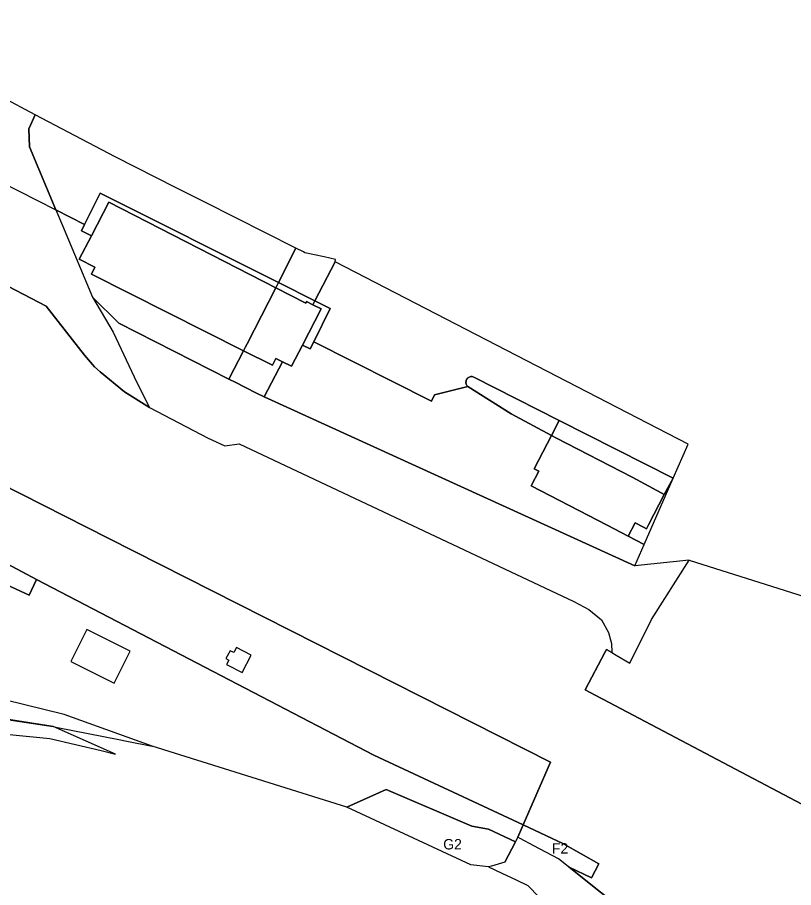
# Model space of a CAD drawing. Extents: x -749314 to -746497, y -1026537 to -1024935.
# Drawn here: x -748054 to -747867.9, y -1025476.4 to -1025267.7 of the extents above; entities that cross this region are included whole.
import ezdxf

# ---------------------------------------------------------------- set-up
doc = ezdxf.new("R2010")
doc.units = 0
for name, color, linetype in [('Default', 7, 'Continuous'), ('K_CD1', 7, 'Continuous'), ('K_DOSZDC1', 7, 'Continuous'), ('K_JVL', 7, 'Continuous'), ('K_NH_SZDC', 7, 'Continuous'), ('K_SZDC1', 7, 'Continuous')]:
    doc.layers.add(name, color=color, linetype=linetype)

msp = doc.modelspace()

# ---------------------------------------------------------------- linework, layer by layer
at = {"layer": 'Default'}
for points in [[(-748259.36, -1025267.68), (-748156.97, -1025329.23), (-748032.2, -1025392.56), (-747926.21, -1025446.35), (-747932.75, -1025461.36), (-747968.57, -1025444.62), (-748049.38, -1025402.52), (-748073.99, -1025389.35), (-748082.88, -1025385.8), (-748108.65, -1025372.85), (-748143.78, -1025358.9), (-748153.5, -1025355.12), (-748164.65, -1025351.55), (-748174.46, -1025348.85), (-748184.1, -1025347.37), (-748182.63, -1025341.82), (-748186.39, -1025340.76), (-748185.38, -1025333.16), (-748213.73, -1025328.27), (-748213.86, -1025329.03), (-748217.05, -1025328.49), (-748217.16, -1025329.19), (-748227.91, -1025325.68), (-748255.65, -1025319)], [(-748057.97, -1025307.14), (-748044.75, -1025313.87), (-748043.19, -1025317.58), (-748035.96, -1025334.78), (-748030.99, -1025343.14), (-748025.38, -1025355.27), (-748022.3, -1025361.24), (-748028.3, -1025357.47), (-748034.14, -1025352.71), (-748035.54, -1025351.47), (-748037.89, -1025348.71), (-748047.05, -1025336.96), (-748057.96, -1025331.28)]]:
    msp.add_lwpolyline(points, dxfattribs=at)
for points in [[(-748035.41, -1025327.58), (-748039.16, -1025325.69), (-748036.26, -1025320.08), (-748038.64, -1025318.9), (-748037.89, -1025317.39), (-748044.75, -1025313.87), (-748043.19, -1025317.58), (-748035.96, -1025334.78), (-748029.7, -1025341.02), (-748003.33, -1025354.49), (-747999.79, -1025347.62), (-748036.24, -1025329.23)], [(-748035.96, -1025334.78), (-748030.99, -1025343.14), (-748025.38, -1025355.27), (-748022.3, -1025361.24), (-748008.28, -1025368.63), (-748004.23, -1025370.41), (-748000.86, -1025369.98), (-747920.59, -1025407.75), (-747917, -1025409.72), (-747913.96, -1025412.2), (-747912.26, -1025415.21), (-747911.57, -1025417.86), (-747911.52, -1025420.04), (-747910.44, -1025420.66), (-747907.16, -1025422.53), (-747901.99, -1025412.07), (-747892.92, -1025397.87), (-747905.98, -1025399.2), (-747994.84, -1025358.7), (-747996.8, -1025357.7), (-748001.6, -1025355.25), (-748003.33, -1025354.49), (-748029.7, -1025341.02)], [(-747945.99, -1025356.21), (-747954.01, -1025358.24), (-747954.73, -1025359.75), (-747982.95, -1025345.52), (-747983.79, -1025347.2), (-747985.65, -1025346.26), (-747988.28, -1025351.35), (-747990.41, -1025350.28), (-747994.84, -1025358.7), (-747905.98, -1025399.2), (-747903.74, -1025394.11), (-747907.58, -1025392.1), (-747912.58, -1025389.5), (-747930.82, -1025380), (-747929.02, -1025376.53), (-747930.09, -1025375.97), (-747925.95, -1025367.99), (-747935.59, -1025362.74)], [(-747994.84, -1025358.7), (-747990.41, -1025350.28), (-747992.03, -1025349.46), (-747992.86, -1025351.11), (-747999.79, -1025347.62), (-748003.33, -1025354.49), (-748001.6, -1025355.25), (-747996.8, -1025357.7)], [(-747924.14, -1025364.33), (-747944.59, -1025353.94), (-747944.94, -1025353.84), (-747945.31, -1025353.84), (-747945.66, -1025353.94), (-747945.98, -1025354.14), (-747946.09, -1025354.24), (-747946.31, -1025354.54), (-747946.44, -1025354.88), (-747946.47, -1025355.25), (-747946.4, -1025355.61), (-747946.24, -1025355.94), (-747945.99, -1025356.21), (-747935.59, -1025362.74), (-747925.95, -1025367.99)], [(-747898.92, -1025382.15), (-747896.76, -1025378.2), (-747924.14, -1025364.33), (-747925.95, -1025367.99), (-747924.88, -1025368.55), (-747906.59, -1025377.99), (-747899.69, -1025381.75)], [(-747898.92, -1025382.15), (-747902.66, -1025389.38), (-747903.15, -1025390.32), (-747903.92, -1025389.92), (-747905.9, -1025388.91), (-747907.58, -1025392.1), (-747903.74, -1025394.11), (-747896.76, -1025378.2)], [(-747997.91, -1025420.63), (-748001.49, -1025418.81), (-748002.12, -1025420.05), (-748003, -1025419.61), (-748003.98, -1025421.48), (-748003.29, -1025421.83), (-748003.83, -1025422.9), (-748000.07, -1025424.84)], [(-748003.98, -1025421.48), (-748003.29, -1025421.83), (-748003.83, -1025422.9), (-748000.07, -1025424.84), (-747997.91, -1025420.63), (-748001.49, -1025418.81), (-748002.12, -1025420.05), (-748003, -1025419.61)], [(-747974.99, -1025457.07), (-747965.57, -1025452.88), (-747945.01, -1025461.7), (-747941.02, -1025462.36), (-747934.61, -1025465.41), (-747937.12, -1025470.28), (-747940.3, -1025471.24), (-747941.01, -1025471.45), (-747945.26, -1025470.98)], [(-747930.17, -1025466.36), (-747933.49, -1025464.6), (-747934.04, -1025464.31), (-747937.12, -1025470.28), (-747940.3, -1025471.24), (-747941.01, -1025471.45), (-747937.86, -1025472.92), (-747934.45, -1025474.52), (-747931.59, -1025475.86), (-747928.91, -1025478.73), (-747876.17, -1025514.34), (-747839.67, -1025538.87), (-747860, -1025524.32), (-747873.67, -1025507.89), (-747876.37, -1025512.29), (-747887.27, -1025505.61), (-747884.53, -1025501.19), (-747924.24, -1025469.51)]]:
    msp.add_lwpolyline(points, close=True, dxfattribs=at)
at = {"layer": 'K_CD1'}
for points in [[(-747992.07, -1025332.51), (-747991.43, -1025331.25), (-748034.12, -1025309.81), (-748037.89, -1025317.39), (-748038.64, -1025318.9), (-748036.26, -1025320.08), (-748032.06, -1025311.97)], [(-747999.41, -1025346.89), (-747998.94, -1025345.97), (-747992.07, -1025332.51), (-748032.06, -1025311.97), (-748036.26, -1025320.08), (-748039.16, -1025325.69), (-748035.41, -1025327.58), (-748036.24, -1025329.23), (-747999.79, -1025347.62)], [(-747988.28, -1025351.35), (-747985.65, -1025346.26), (-747981.19, -1025337.62), (-747983.2, -1025336.59), (-747984.66, -1025335.84), (-747984.85, -1025336.21), (-747992.07, -1025332.51), (-747998.94, -1025345.97), (-747999.41, -1025346.89), (-747999.79, -1025347.62), (-747992.86, -1025351.11), (-747992.03, -1025349.46), (-747990.41, -1025350.28)], [(-747983.2, -1025336.59), (-747982.7, -1025335.64), (-747991.43, -1025331.25), (-747992.07, -1025332.51), (-747984.85, -1025336.21), (-747984.66, -1025335.84)], [(-747982.7, -1025335.64), (-747983.2, -1025336.59), (-747981.19, -1025337.62), (-747985.65, -1025346.26), (-747983.79, -1025347.2), (-747982.95, -1025345.52), (-747978.97, -1025337.51)], [(-748115.84, -1025423.38), (-748116.01, -1025426.66), (-748045.39, -1025437.77), (-748044.41, -1025437.98), (-748029.7, -1025440.89), (-748027.77, -1025441.28), (-748021.66, -1025442.5), (-748042.77, -1025434.89), (-748061.7, -1025430.24), (-748111.52, -1025421.94), (-748150.48, -1025415.41), (-748150.78, -1025415.18), (-748163.17, -1025405.57), (-748151.61, -1025420.44), (-748137.8, -1025422.95), (-748137.76, -1025422.13)], [(-748149.03, -1025434.28), (-748138.93, -1025443.46), (-748137.83, -1025443.74), (-748131.63, -1025445.33), (-748123.33, -1025444.53), (-748094.04, -1025441.72), (-748063.99, -1025438.84), (-748046.18, -1025440.63), (-748033.92, -1025443.55), (-748030.5, -1025444.36), (-748045.39, -1025437.77), (-748064.07, -1025434.97), (-748084.21, -1025436.6), (-748123.99, -1025441.67), (-748131.48, -1025440.38), (-748138.81, -1025436.89), (-748151.61, -1025420.44), (-748166.47, -1025409.42)], [(-748026.92, -1025419.73), (-748037.3, -1025414.46), (-748041.17, -1025422.13), (-748030.77, -1025427.38)], [(-748026.92, -1025419.73), (-748037.3, -1025414.46), (-748041.17, -1025422.13), (-748030.77, -1025427.38)], [(-748151.61, -1025420.44), (-748138.81, -1025436.89), (-748131.48, -1025440.38), (-748123.99, -1025441.67), (-748084.21, -1025436.6), (-748064.07, -1025434.97), (-748045.39, -1025437.77), (-748116.01, -1025426.66), (-748116.07, -1025427.79), (-748115.16, -1025427.84), (-748115.25, -1025429.55), (-748116.16, -1025429.5), (-748116.6, -1025437.71), (-748138.47, -1025436.54), (-748138.19, -1025430.94), (-748139.96, -1025430.85), (-748139.84, -1025427.7), (-748138.04, -1025427.78), (-748137.8, -1025422.95)], [(-747884.53, -1025501.19), (-747924.24, -1025469.51), (-747930.17, -1025466.36), (-747933.49, -1025464.6), (-747934.04, -1025464.31), (-747926.21, -1025446.35), (-747932.75, -1025461.36), (-747923.1, -1025465.87), (-747914.56, -1025470.67), (-747916.35, -1025474.07), (-747921.73, -1025471.52)]]:
    msp.add_lwpolyline(points, close=True, dxfattribs=at)
for points in [[(-748073.99, -1025389.35), (-748049.38, -1025402.52), (-748051.19, -1025406.25), (-748070.97, -1025397.13)], [(-748070.97, -1025397.13), (-748051.19, -1025406.25), (-748049.38, -1025402.52), (-747968.57, -1025444.62), (-747932.75, -1025461.36), (-747934.04, -1025464.31), (-747937.12, -1025470.28), (-747934.61, -1025465.41), (-747941.02, -1025462.36), (-747945.01, -1025461.7), (-747965.57, -1025452.88), (-747974.99, -1025457.07), (-748021.66, -1025442.5), (-748042.77, -1025434.89), (-748061.7, -1025430.24)]]:
    msp.add_lwpolyline(points, dxfattribs=at)
at = {"layer": 'K_DOSZDC1'}
for points in [[(-747860, -1025524.32), (-747873.67, -1025507.89), (-747884.53, -1025501.19), (-747921.73, -1025471.52), (-747916.35, -1025474.07), (-747914.56, -1025470.67), (-747923.1, -1025465.87), (-747932.75, -1025461.36), (-747926.21, -1025446.35), (-748032.2, -1025392.56), (-748156.97, -1025329.23), (-748259.36, -1025267.68)], [(-748057.96, -1025331.28), (-748047.05, -1025336.96), (-748037.89, -1025348.71), (-748035.54, -1025351.47), (-748034.14, -1025352.71), (-748028.3, -1025357.47), (-748022.3, -1025361.24), (-748008.28, -1025368.63), (-748004.23, -1025370.41), (-748000.86, -1025369.98), (-747920.59, -1025407.75), (-747917, -1025409.72), (-747913.96, -1025412.2), (-747912.26, -1025415.21), (-747911.57, -1025417.86), (-747911.52, -1025420.04), (-747912.78, -1025419.32), (-747913.16, -1025420.04), (-747917.87, -1025428.97), (-747915.46, -1025430.24), (-747912.12, -1025432), (-747865.91, -1025456.37)], [(-747645.99, -1025568.28), (-747732.3, -1025526.84), (-747772.49, -1025505.64), (-747865.91, -1025456.37), (-747912.12, -1025432), (-747915.46, -1025430.24), (-747917.87, -1025428.97), (-747913.16, -1025420.04), (-747912.78, -1025419.32), (-747911.52, -1025420.04), (-747910.44, -1025420.66), (-747907.16, -1025422.53), (-747901.99, -1025412.07), (-747892.92, -1025397.87), (-747869.93, -1025405.14), (-747846.49, -1025412.54), (-747841.03, -1025414.26), (-747808.54, -1025424.53), (-747801.54, -1025426.74), (-747806.89, -1025440.81), (-747803.65, -1025456.55), (-747724.81, -1025501.31), (-747681.55, -1025522.63), (-747651.76, -1025538.04)]]:
    msp.add_lwpolyline(points, dxfattribs=at)
at = {"layer": 'K_JVL'}
msp.add_lwpolyline([(-748057.97, -1025307.14), (-748044.75, -1025313.87), (-748051.12, -1025298.75), (-748051.28, -1025294.41), (-748049.7, -1025291.02), (-748065.92, -1025282.45)], dxfattribs=at)
for points in [[(-748037.89, -1025317.39), (-748034.12, -1025309.81), (-747991.43, -1025331.25), (-747987.22, -1025323.01), (-748009.05, -1025311.99), (-748015.9, -1025308.53), (-748030.54, -1025301.15), (-748049.7, -1025291.02), (-748051.28, -1025294.41), (-748051.12, -1025298.75), (-748044.75, -1025313.87)], [(-747982.7, -1025335.64), (-747977.81, -1025326.34), (-747977.7, -1025325.73), (-747980.41, -1025325.13), (-747985.06, -1025324.11), (-747985.41, -1025323.93), (-747987.22, -1025323.01), (-747991.43, -1025331.25)], [(-747978.97, -1025337.51), (-747982.95, -1025345.52), (-747954.73, -1025359.75), (-747954.01, -1025358.24), (-747945.99, -1025356.21), (-747946.24, -1025355.94), (-747946.4, -1025355.61), (-747946.47, -1025355.25), (-747946.44, -1025354.88), (-747946.39, -1025354.73), (-747946.23, -1025354.41), (-747945.98, -1025354.14), (-747945.66, -1025353.94), (-747945.31, -1025353.84), (-747944.94, -1025353.84), (-747944.59, -1025353.94), (-747924.14, -1025364.33), (-747896.76, -1025378.2), (-747893.2, -1025370.08), (-747977.81, -1025326.34), (-747982.7, -1025335.64)]]:
    msp.add_lwpolyline(points, close=True, dxfattribs=at)
at = {"layer": 'K_NH_SZDC'}
for points in [[(-748049.38, -1025402.52), (-747968.57, -1025444.62), (-747932.75, -1025461.36)], [(-747974.99, -1025457.07), (-747965.57, -1025452.88), (-747945.01, -1025461.7), (-747941.02, -1025462.36), (-747934.61, -1025465.41)], [(-747932.75, -1025461.36), (-747923.1, -1025465.87), (-747914.56, -1025470.67), (-747916.35, -1025474.07), (-747921.73, -1025471.52)]]:
    msp.add_lwpolyline(points, dxfattribs=at)
at = {"layer": 'K_SZDC1'}
msp.add_lwpolyline([(-747929.02, -1025376.53), (-747930.82, -1025380), (-747912.58, -1025389.5), (-747907.58, -1025392.1), (-747905.9, -1025388.91), (-747903.92, -1025389.92), (-747903.15, -1025390.32), (-747902.66, -1025389.38), (-747898.92, -1025382.15), (-747899.69, -1025381.75), (-747906.59, -1025377.99), (-747924.88, -1025368.55), (-747925.95, -1025367.99), (-747930.09, -1025375.97)], close=True, dxfattribs=at)

# ---------------------------------------------------------------- texts
for s, p in [('G2', (-747951.9, -1025467.25)), ('F2', (-747925.84, -1025468.25))]:
    msp.add_text(s, height=2.5).set_placement(p)

doc.saveas('drawing.dxf')
